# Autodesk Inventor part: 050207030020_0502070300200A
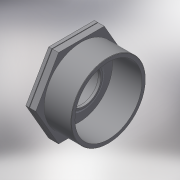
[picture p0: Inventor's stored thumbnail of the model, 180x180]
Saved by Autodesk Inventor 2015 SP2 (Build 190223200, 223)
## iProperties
Created: 2017-05
Part Number: 050207030020_0502070300200A
Material: Generic
Description: PLASSON REDUCING BUSHING 3"-2"
Document SubType Name: Modeling
Designer: KIM
Density: 1 g/cm^3
Appearance: Default
Author: KIM
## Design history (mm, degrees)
derived "050207.ipt"
feature "Solid1::050207.ipt"
tag "TaggingFeature1"
body "Solid1"
other parameters: "d1" = 87.884, "d5" = 32, "d8" = 0.48, "d12" = 0, "d15" = 48, "d19" = 0, "d30" = 9.6, "d31" = 4.8, "d33" = 56.656, "d34" = 79.0956, "d36" = 4.5, "d37" = 67.9872, "d38" = 31.68, "d39" = 50.9904, "d40" = 3.2, "d41" = 0, "H_" = 48, "R_" = 87.884, "l_2" = 32, "Rp_" = 56.656
